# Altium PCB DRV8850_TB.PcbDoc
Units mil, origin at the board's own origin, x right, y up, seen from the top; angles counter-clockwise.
Board outline 575 x 1700 mil, 2 copper layers (Top Layer, Bottom Layer), stack 62 mil thick; 41 components, 20 nets, 99 pads, 47 vias.
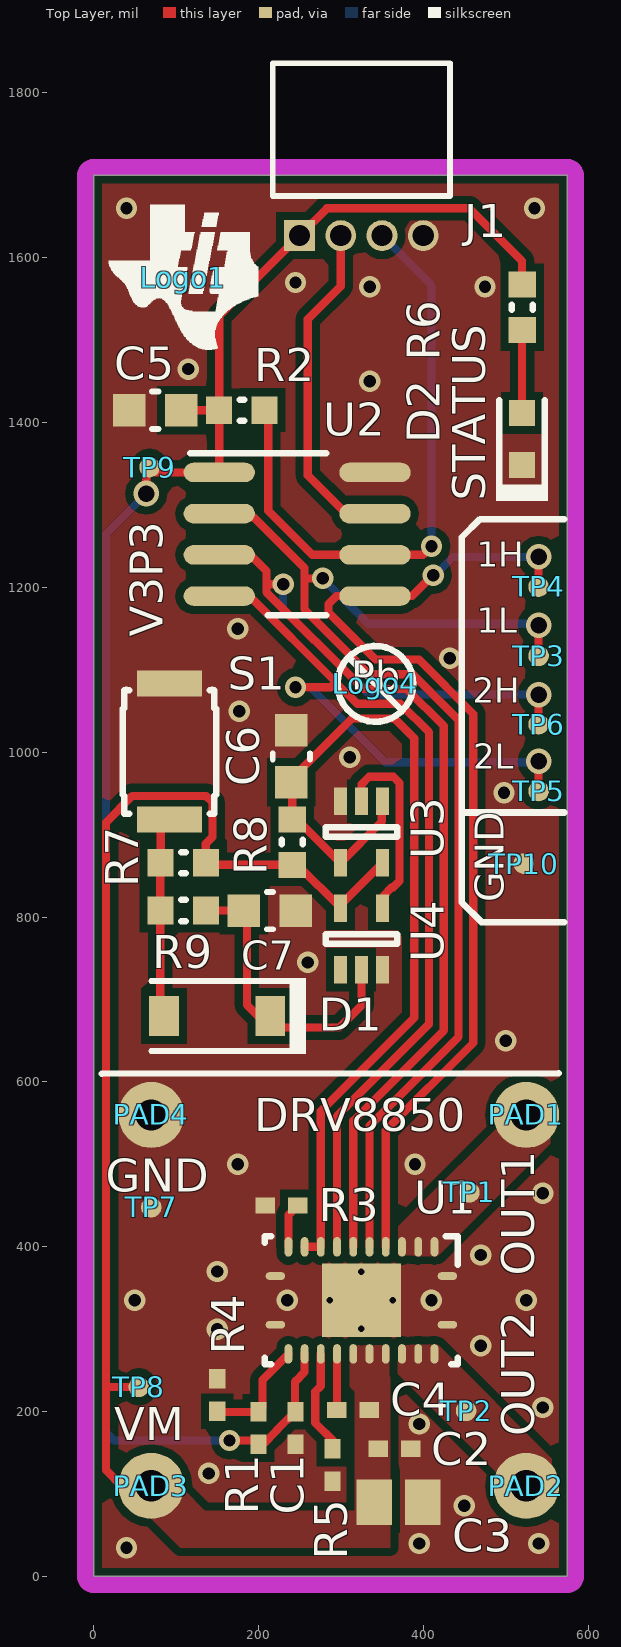
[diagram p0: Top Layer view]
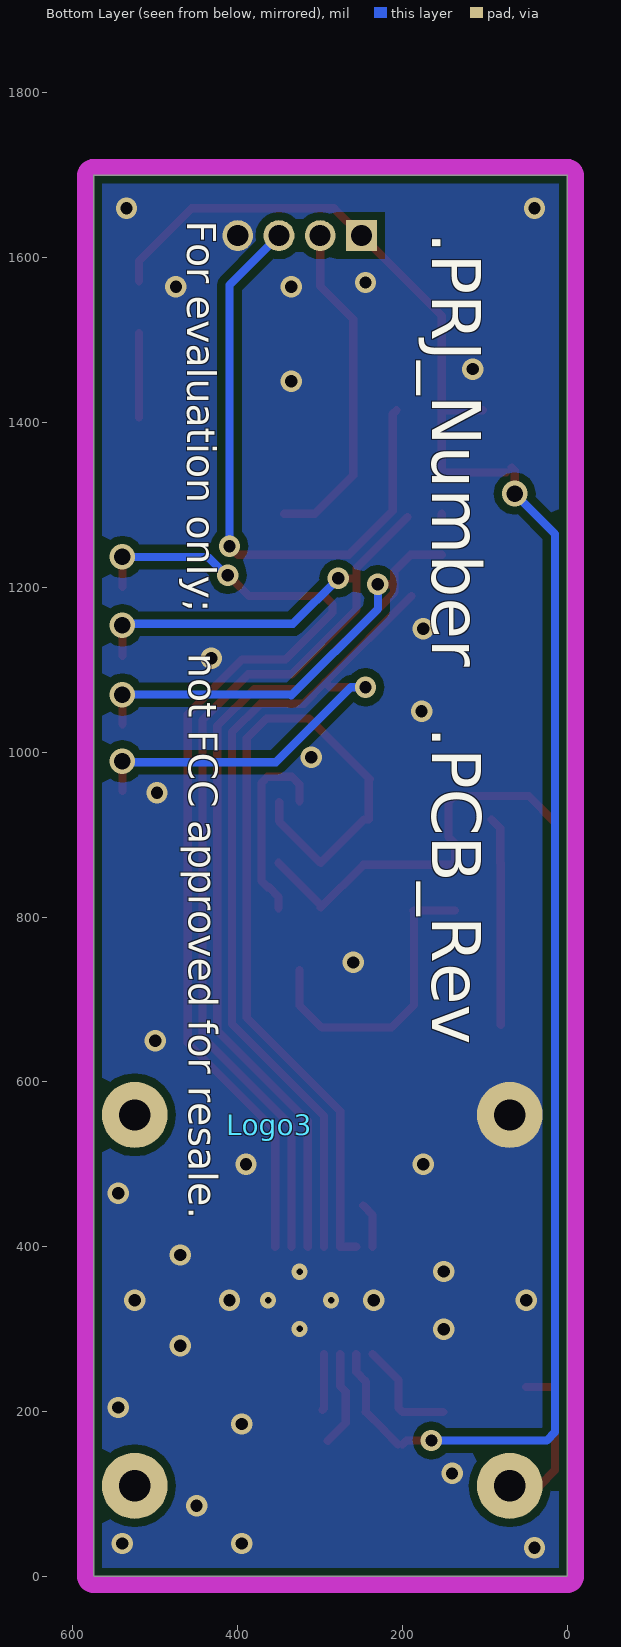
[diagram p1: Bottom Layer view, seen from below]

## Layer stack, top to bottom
Top Solder: solder mask 0.4, Solder Resist, Dk 3.5
Top Layer: signal copper 1.4
Dielectric1: core 59.2, FR-4, Dk 4.8
Bottom Layer: signal copper 1.4
Bottom Solder: solder mask 0.4, Solder Resist, Dk 3.5

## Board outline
0,0 575,0 575,1700 0,1700

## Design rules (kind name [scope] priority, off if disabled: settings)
AcuteAngle [All] p1: minimum=4.50000000000000E+0001 checktracksonly=FALSE
AssemblyTestPointUsage [All] p1: valid=2
Clearance Clearance_Keepouts [((IsTrack Or IsArc) And Not InPoly) And IsFree and IsKeepOut vs ((IsTrack Or IsArc) And Not InPoly) And IsFree and IsKeepOut] p1: gap=0
Clearance Clearance_BoardEdge_MountingHoles [OnCopper and InComponentClass('Mounting Holes') vs IsKeepOut] p2: gap=40
Clearance Clearance_BoardEdge_Poly [OnCopper and InPoly vs IsKeepOut] p3: gap=10
Clearance Clearance_BoardEdge [OnCopper and Not InComponentClass('Logo') and not InComponentClass('FiducialMark') and not InRegion(1000,500,4000,800) and Not IsKeepout vs IsKeepOut] p4: gap=10
Clearance Clearance_Poly [InPolygon] p5: gap=10
Clearance [All] p6: gap=7.87
ComponentClearance ComponentClearance_MountingHoles_FiducialMarks [InComponentClass('Mounting Holes') vs InComponentClass('FiducialMark')] p1: gap=50 collisioncheckmode=3 verticalgap=10 showdistances=FALSE
ComponentClearance ComponentClearance_Shunt [InComponentClass('Header') vs InComponentClass('Shunt')] p2: gap=0 collisioncheckmode=3 verticalgap=0 showdistances=FALSE
ComponentClearance ComponentClearance_Logo [InComponentClass('Logo')] p3: gap=40 collisioncheckmode=3 verticalgap=10 showdistances=FALSE
ComponentClearance ComponentClearance_ScrewToNut [(HasFootprint('NY PMS 440 0025 PH')) vs (HasFootprint('Keystone_1902C'))] p4: gap=5 collisioncheckmode=3 verticalgap=10 showdistances=FALSE
ComponentClearance ComponentClearance_MountingHoles [InComponentClass('Mounting Holes')] p5: gap=250 collisioncheckmode=3 verticalgap=100000 showdistances=FALSE
ComponentClearance ComponentClearance_SmallPassives [HasFootprint('0201*') or HasFootprint('0402*') or HasFootprint('0508') or HasFootprint('0603*') or HasFootprint('0612') or HasFootprint('0805*') or HasFootprint('0815*') or HasFootprint('0830*') or HasFootprint('1206*') or HasFootprint('1210*') or HasFootprint('1808*') or HasFootprint('1812*') or HasFootprint('1825*') or HasFootprint('2010*') or HasFootprint('2220*') or HasFootprint('2225*') or HasFootprint('2512*') or HasFootprint('2728*') or HasFootprint('3518*') vs HasFootprint('0201*') or HasFootprint('0402*') or HasFootprint('0508') or HasFootprint('0603*') or HasFootprint('0612') or HasFootprint('0805*') or HasFootprint('0815*') or HasFootprint('0830*') or HasFootprint('1206*') or HasFootprint('1210*') or HasFootprint('1808*') or HasFootprint('1812*') or HasFootprint('1825*') or HasFootprint('2010*') or HasFootprint('2220*') or HasFootprint('2225*') or HasFootprint('2512*') or HasFootprint('2728*') or HasFootprint('3518*')] p6: gap=20 collisioncheckmode=3 verticalgap=10 showdistances=FALSE
ComponentClearance ComponentClearance_THtoSMT [IsThruComponent vs IsSMTComponent] p7: gap=30 collisioncheckmode=3 verticalgap=30 showdistances=FALSE
ComponentClearance ComponentClearance_THtoTH [IsThruComponent vs IsThruComponent] p8: gap=60 collisioncheckmode=3 verticalgap=30 showdistances=FALSE
ComponentClearance [All] p9: gap=12 collisioncheckmode=3 verticalgap=10 showdistances=FALSE
DiffPairsRouting [All] p1: maxlimit=100 minlimit=10 mostfreqgap=10 toplayer_minwidth=15 toplayer_maxwidth=15 toplayer_prefwidth=15 bottomlayer_minwidth=15 bottomlayer_maxwidth=15 bottomlayer_prefwidth=15 maxuncoupledlength=1000
FabricationTestPointUsage TestPointUsage [All] p1: valid=2 allowmultiple=FALSE
FabricationTestpoint Testpoint [All] p1: side=3 testpointundercomponent=TRUE minsize=40 maxsize=100 preferedsize=60 minholesize=0 maxholesize=40 preferedholesize=32 testpointgrid=1 allowsidetop=TRUE allowsidebottom=TRUE usegrid=TRUE gridtolerance=0.01
FanoutControl Fanout_LCC [IsLCC] p1: bgadir=Out bgaviamode=Centered fanoutstyle=Auto fanoutdirection=Alternating viagrid=1 // Fanout_LCC (Default Rule)
FanoutControl Fanout_BGA [IsBGA] p2: bgadir=Out bgaviamode=Centered fanoutstyle=Auto fanoutdirection=Alternating viagrid=1 // Fanout_BGA (Default Rule)
FanoutControl Fanout_Default [All] p4: bgadir=Out bgaviamode=Centered fanoutstyle=Auto fanoutdirection=Alternating viagrid=1 // Fanout_Default (Default Rule)
FanoutControl Fanout_Small [(CompPinCount < 5)] p5: bgadir=Out bgaviamode=Centered fanoutstyle=Auto fanoutdirection=OutThenIn viagrid=1 // Fanout_Small (Default Rule)
HoleSize [All] p1: absolutevalues=TRUE maxlimit=251 minlimit=7.8 maxpercent=80.000 minpercent=20.000
MinimumAnnularRing MinimumAnnularRing_ThermalPadVias [IsVia and InAnyComponent] p1: minimumring=5.91
MinimumAnnularRing [All] p2: minimumring=5.5
MinimumSolderMaskSliver MinimumSolderMaskSliver_Logo [InComponentClass('Logo') vs InComponentClass('Logo')] p1: minsoldermaskwidth=0.7
MinimumSolderMaskSliver [All] p2: minsoldermaskwidth=3.94
PlaneConnect [All] p1: planeconnectstyle=Direct reliefexpansion=10 reliefentries=4 reliefconductorwidth=10 reliefairgap=10
PolygonConnect [All] p1: connectstyle=Direct reliefconductorwidth=10 reliefentries=4 polygonreliefangle="90 Angle" airgapwidth=10
RoutingVias ThermalPadVias [IsVia and InAnyComponent] p1: holewidth=7.87 width=19.68 viastyle="Through Hole" minholewidth=7.87 minwidth=19.68 maxholewidth=12.99 maxwidth=23.62
RoutingVias [All] p2: holewidth=16 width=34 viastyle="Through Hole" minholewidth=7.87 minwidth=26 maxholewidth=40 maxwidth=65
SilkToBoardRegionClearance [Not ((IsComment or IsDesignator) And (Hide <> 'False')) and not InRegion(1000,500,4000,800)] p1:
SilkToSilkClearance SilkToSilkClearance_Pb-FreeLogo [(HasFootprint('Pb-Free_Overlay_Medium') OR HasFootprint('Pb-Free_Overlay_Small')) vs (HasFootprint('Pb-Free_Overlay_Medium') OR HasFootprint('Pb-Free_Overlay_Small'))] p1: silktosilkclearance=0
SilkToSilkClearance [All] p2: silktosilkclearance=5
SilkToSolderMaskClearance "Silk to Solder Mask Opening" [All] p1: minsilkscreentomaskgap=1 clearancetoexposedcopper=FALSE
SolderMaskExpansion [All] p1: expansion=1.97
UnpouredPolygon [All] p1: allowunpoured=FALSE
Width [All] p1: maxlimit=100 minlimit=6 preferedwidth=10 checkconnectedcopper=TRUE
14 further rules are at their usual default settings.

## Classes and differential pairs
component class Logo: Logo1

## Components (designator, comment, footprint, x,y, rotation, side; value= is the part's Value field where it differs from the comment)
C1 "885012105013" 0402L 245,180 r270 top
C2 "885012105016" 0402L 365,155 r0 top
C3 "885012207026" 0805_145L 370,90 r0 top
C4 "885012105016" 0402L 315,202 r0 top
C5 "885012206046" 0603_095 75,1415 r180 top
C6 "885012206046" 0603_095 240,995 r90 top
C7 "885012106017" 0603_095 214,808 r0 top
D1 "1N4148W-7-F" SOD-123 150,680 r180 top
D2 "150060VS75000" WL-SMCW_GREEN 520,1380 r90 top
J1 "851-43-004-20-001000" CONN_851-43-004-20-001000 325,1627 r180 top
Logo1 "Texas Instruments" TI_Symbol_Overlay_Small 109,1576 r0 top
Logo3 "FCC disclaimer" FCC_disclaimer_stacked 361.28,548 r270 bottom
Logo4 "Pb-Free Symbol" Pb-Free_Overlay_Small 342,1083 r0 top
PAD1 "OUT1" TESTPOINT 525,560 r0 top
PAD2 "OUT2" TESTPOINT 525,110 r90 top
PAD3 "VM" TESTPOINT 70,110 r0 top
PAD4 "GND" TESTPOINT 70,560 r0 top
R1 "CRCW0402127KFKED" 0402L 200,180 r270 top
R2 "CRCW060347K0JNEA" 0603L 180,1415 r0 top
R3 "CRCW04022K40JNED" 0402L 228,450 r180 top
R4 "CRCW040240K2FKED" 0402L 150,220 r270 top
R5 "CRCW04021K00FKED" 0402L 290,135 r90 top
R6 "CRCW060362R0JNEA" 0603L 520,1540 r90 top
R7 "CRCW060320K0JNEA" 0603L 109,866 r0 top
R8 "DNP" 0603L 241,891 r270 top
R9 "CRCW060320K0JNEA" 0603L 109,808 r180 top
S1 "SKRKAEE010" SW_SKRKAEE010 92,1001 r270 top
TP1 "OUT1" TP_25MIL-SMT 456,466 r90 top
TP2 "OUT2" TP_25MIL-SMT 452,201 r90 top
TP3 "1L" TP_25MIL-SMT 540,1117 r90 top
TP4 "1H" TP_25MIL-SMT 540,1201 r90 top
TP5 "2L" TP_25MIL-SMT 540,953 r90 top
TP6 "2H" TP_25MIL-SMT 540,1034 r90 top
TP7 "GND" TP_25MIL-SMT 70,448 r90 top
TP8 "VM" TP_25MIL-SMT 55,230 r90 top
TP9 "V3P3" TP_25MIL-SMT 68,1346 r90 top
TP10 "GND" TP_25MIL-SMT 522,865 r90 top
U1 "DRV8850RGY" RGY0024B 325,335 r270 top
U2 "MSP430G2210IDR" D0008A_N 247.05,1264.58 r0 top
U3 "SN74LVC1G80DCK" DCK0005A_N 325,903.31 r270 top
U4 "SN74LVC1G14DCK" DCK0005A_N 325,773.31 r90 top

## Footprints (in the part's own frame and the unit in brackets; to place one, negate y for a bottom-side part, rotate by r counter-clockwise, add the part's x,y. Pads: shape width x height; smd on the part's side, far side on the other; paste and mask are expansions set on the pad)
0402L [mm] "0402 from SM-752 data"
  rect 0.6x0.5 smd: 1(-0.5,0) 2(0.5,0)
  body extent -0.55,-0.3 0.55,0.3, height 0.6
0603_095 [mm] "0603_095"
  rect 1x1 smd: 1(-0.8,0) 2(0.8,0)
  silkscreen extent -0.1,-0.58 0.1,0.58, body extent -0.87,-0.48 0.87,0.48, height 0.95
0603L [mm] "0603 from SM-752 data"
  rect 0.8x0.85 smd: 1(-0.7,0) 2(0.7,0)
  silkscreen extent -0.07,-0.33 0.07,0.33, body extent -0.87,-0.47 0.87,0.47, height 0.85
0805_145L [mm] "0805 / 1.45mm height"
  rect 1.1x1.4 smd: 1(-0.75,0) 2(0.75,0)
  body extent -1.1,-0.72 1.1,0.72, height 1.45
CONN_851-43-004-20-001000 [mm] "MILL-MAX"
  rect 0.95x0.95 hole 0.65: 1(1.905,0)
  round 0.95 hole 0.65: 2(0.635,0) 3(-0.635,0) 4(-1.905,0)
  silkscreen extent -2.73,-5.31 2.73,-1.22, body extent -2.73,-5.31 2.73,0.23, height 2.23
D0008A_N [mm] "SOIC, 8-Leads, Body 4.9x3.9mm, Pitch 1.27mm, IPC Medium Density"
  oval 2.2x0.6 smd: 1(-2.4,1.905) 2(-2.4,0.635) 3(-2.4,-0.635) 4(-2.4,-1.905) 5(2.4,-1.905) 6(2.4,-0.635) 7(2.4,0.635) 8(2.4,1.905)
  silkscreen extent -3.3,-2.5 0.9,2.5, body extent -3,-2.45 3,2.45, height 1.63
DCK0005A_N [mm] "SOT353, 5-Leads, Body 2x1.3mm, Pitch 0.65mm, Lead Span 2.1mm, IPC Medium Density"
  rect 0.85x0.4 smd: 1(-0.95,0.65) 2(-0.95,0) 3(-0.95,-0.65) 4(0.95,-0.65) 5(0.95,0.65)
  silkscreen extent -0.15,-1.1 0.15,1.1, body extent -1.14,-1 1.14,1, height 0.94
FCC_disclaimer_stacked [mil]
Pb-Free_Overlay_Small [mil]
  silkscreen extent -46,-46 46,46
RGY0024B [mm] "QFN, 24-Leads, Body 5.5x3.5mm, Pitch 0.5mm, Thermal Pad 4.05x2.05mm, TI Recommended"
  oval 0.24x0.6 smd: 1(-0.75,2.65) 12(-0.75,-2.65) 13(0.75,-2.65) 24(0.75,2.65)
  oval 0.6x0.24 smd: 2(-1.65,2.25) 3(-1.65,1.75) 4(-1.65,1.25) 5(-1.65,0.75) 6(-1.65,0.25) 7(-1.65,-0.25) 8(-1.65,-0.75) 9(-1.65,-1.25) 10(-1.65,-1.75) 11(-1.65,-2.25) 14(1.65,-2.25) 15(1.65,-1.75) 16(1.65,-1.25) 17(1.65,-0.75) 18(1.65,-0.25) 19(1.65,0.25) 20(1.65,0.75) 21(1.65,1.25) 22(1.65,1.75) 23(1.65,2.25)
  rect 2.26x2.44 smd paste-1.2: 25(0,0)
  silkscreen extent -1.97,-2.98 1.97,2.98, body extent -1.83,-2.83 1.83,2.82, height 1.01
SOD-123 [mm] "On Semi recommended land pattern"
  rect 0.915x1.22 smd: 1(-1.637,0) 2(1.637,0)
  silkscreen extent -2.74,-1.17 2.03,1.17, body extent -1.93,-0.9 1.93,0.9, height 1.35
SW_SKRKAEE010 [mm] "Alps recommended land pattern"
  rect 0.8x2 smd: 1(-2.1,0) 2(2.1,0)
  silkscreen extent -1.9,-1.44 1.92,1.44, body extent -2.4,-1.45 2.4,1.45, height 1.96
TESTPOINT [mil]
  round 80 hole 37.99: 1(0,0)
TI_Symbol_Overlay_Small [mil]
  silkscreen extent -90,-88 91,88
TP_25MIL-SMT [mil]
  round 25 smd mask-2.5: 1(0,0)
WL-SMCW_GREEN [mm] "WURTH"
  rect 0.8x0.8 smd: 1(-0.8,0) 2(0.8,0)
  silkscreen extent -1.9,-0.8 1.2,0.8, body extent -0.85,-0.45 0.85,0.45, height 0.8

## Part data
C1: "CAP, CERM, 2.2 µF, 10 V, +/- 20%, X5R, 0402"
C2 C4: "CAP, CERM, 0.1 µF, 16 V, +/- 20%, X5R, 0402"
C3: "CAP, CERM, 10 µF, 10 V, +/- 10%, X7R, 0805"
C5 C6: "CAP, CERM, 0.1 µF, 16 V, +/- 10%, X7R, 0603_095"
C7: "CAP, CERM, 1 µF, 16 V, +/- 20%, X5R, 0603_095"
D1: "Diode, Ultrafast, 100 V, 0.15 A, SOD-123"
D2: "LED, Green, SMD"
J1: "SOCKET .050\" GRID SIP 4 POS R/A, TH"
Logo1: library part TI_Logo, "Texas Instrument Corporate Signature"
Logo3: library part FCC_disclaimer, "FCC_disclaimer"
Logo4: library part Pb-Free
PAD1 PAD2 PAD3 PAD4 TP1 TP2 TP3 TP4 TP5 TP6 TP7 TP8 TP9 TP10: library part TESTPOINT, "TEST POINT.  No entry in BOM."
R1: "RES, 127k ohm, 1%, 0.063W, 0402"
R2: "RES, 47k ohm, 5%, 0.1W, 0603"
R3: "RES, 2.4k ohm, 5%, 0.063W, 0402"
R4: "RES, 40.2k ohm, 1%, 0.063W, 0402"
R5: "RES, 1.00k ohm, 1%, 0.063W, 0402"
R6: "RES, 62, 5%, 0.1 W, 0603"
R7 R9: "RES, 20k ohm, 5%, 0.1W, 0603"
R8: library part CRCW06030000Z0EA, "RES, 0 ohm, 5%, 0.1W, 0603"
S1: "Switch, Push Button, SMD"
U1: "Low-Voltage H-Bridge IC With LDO Regulator, RGY0024B"
U2: "MIXED SIGNAL MICROCONTROLLER, D0008A"
U3: library part SN74LVC1G80DBV, "IC, Single Positive-Edge-Triggered D-Type Flip-Flop"
U4: "IC, Single Schmitt-Trigger Inverter"

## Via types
v1: diameter 26, hole 15, Top Layer to Bottom Layer, tented both sides, 36 vias
v2: diameter 31, hole 20, Top Layer to Bottom Layer, 5 vias
v3: diameter 19.68, hole 7.87, Top Layer to Bottom Layer, 4 vias
v4: diameter 26, hole 15, Top Layer to Bottom Layer, 2 vias

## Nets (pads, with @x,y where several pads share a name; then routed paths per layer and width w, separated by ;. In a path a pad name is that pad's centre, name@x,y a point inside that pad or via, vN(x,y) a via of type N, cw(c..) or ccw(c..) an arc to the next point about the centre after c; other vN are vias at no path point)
GND: C1.2 C2.2 C3.2 C5.2 C6.2 C7.2 D2.1 J1.4 PAD4.1 R3.2 R4.1 R5.1 S1.1 TP7.1 TP10.1 U1.1 U1.12 U1.13 U1.24 U1.25 U2.8 U3.3 U4.3
  other v1: 40,35 395,40 540,40 450,86 140,125 395,185 545,205 470,280 150,300 50,335 235,335 410,335 525,335 150,370 470,390 545,465 175,500 390,500 500,650 260,745 498,951 311,994 177,1050 432,1114 175,1150 335,1450 115,1465 335,1565 475,1565 245,1570 40,1660 535,1660
  other v3: 325,300.35 286.81,335 363.19,335 325,369.65
IN1H: TP4.1 U1.5 U2.5 | length 1248.7
  Top Layer w10: U1.5 354.53,541.25 460.71,647.43 460.71,1046.57 394.78,1112.5 342.21,1112.5 285,1169.71 285,1180 294.58,1189.58 U2.5 386.58,1189.58 v1(412,1215) ; TP4.1 v2(540,1237)
  Bottom Layer w10: v1(412,1215) 410,1217 413,1220 416,1217 436,1237 v2(540,1237)
IN1L: TP3.1 U1.6 U2.2 | length 1410.4
  Top Layer w10: U2.2@152.56,1283.08 U2.2 ; U2.2@194.17,1285.55 256,1223.72 256,1173.43 334.81,1094.62 387.38,1094.62 442.83,1039.17 442.83,654.83 334.84,546.84 U1.6 ; 258,1211 v4(278,1211) ; TP3.1 v2(540,1154)
  Bottom Layer w10: v4(278,1211) 333,1156 v2@538,1156
IN2H: TP6.1 U1.7 U2.3 | length 1489.7
  Top Layer w10: U2.3 190.42,1239.58 210,1220 210,1194.15 327.4,1076.75 379.97,1076.75 424.96,1031.76 424.96,662.68 315.16,552.88 U1.7 ; 211,1204 v4(230,1204) ; TP6.1 v2(540,1070)
  Bottom Layer w10: v4(230,1204) 230,1174.15 335.15,1069 336.15,1070 v2(540,1070)
IN2L: TP5.1 U1.8 U2.4 | length 1375.9
  Top Layer w10: U2.4@189.29,1189.58 293.87,1085 ; v1(245,1079) 287.87,1079 293.87,1085 ; U1.8 295.47,558.47 407.09,670.09 407.09,1024.36 372.57,1058.87 320,1058.87 293.87,1085 ; TP5.1 v2(540,989)
  Bottom Layer w10: v1(245,1079) 262.59,1079 353.59,988 v2@539,988
NetC4_1: C4.1 U1.17 | length 68.8
  Top Layer w10: U1.17 295.47,203.84 C4.1@297.32,202
NetC7_1: C7.1 D1.1 R9.1 U4.2 | length 368.6
  Top Layer w10: R9.1 C7.1@186.44,808 ; C7.1@186.06,807.62 186.06,693.41 213.47,666 298.21,666 325,692.79 U4.2
NetD1_2: D1.2 R7.1 R9.2 S1.2 | length 252.2
  Top Layer w10: R7.1@81,865 D1.2@81.06,669.48 ; R7.1 81.44,907.76 S1.2
NetD2_2: D2.2 R6.1 | length 102.4
  Top Layer w10: D2.2@520,1406.09 R6.1@520,1508.5
NetR1_1: R1.1 R4.2 U1.14 | length 134.8
  Top Layer w10: R4.2@150.63,199.68 R1.1 204.95,204.63 204.95,238.57 U1.14
NetR3_1: R3.1 U1.11 | length 54.7
  Top Layer w10: U1.11 236.42,438.73 R3.1
NetR5_2: R5.2 U1.16 | length 117.5
  Top Layer w10: U1.16 275.79,231.1 269,224.32 269,186.43 R5.2@290.95,164.48
NetU3_2: U3.2 U4.4 | length 235.3
  Top Layer w10: U3.2 325,961.2 334.12,970.32 363.8,970.32 371.34,962.78 371.34,843.85 363.8,836.31 362.31,836.31 350.59,824.59 U4.4
OUT1: PAD1.1 TP1.1 U1.2 U1.3 U1.4
OUT2: PAD2.1 TP2.1 U1.21 U1.22 U1.23
SBWTCK: J1.2 U2.7 | length 410.9
  Top Layer w10: J1.2 300,1565.59 260,1525.59 260,1335.88 306.3,1289.58 U2.7 U2.7@344.05,1289.58
SBWTDIO: J1.3 R2.2 U2.6 | length 750.2
  Top Layer w10: R2.2 212.05,1410.51 212.05,1292.95 265.42,1239.58 U2.6 399.63,1239.58 v1(410.05,1250)
  Bottom Layer w10: J1.3 410,1567 410,1360 410.05,1359.95 v1(410.05,1250)
TOGGLE: C6.1 R8.1 U1.9 U1.10 U3.1 U3.4 | length 1098.1
  Top Layer w10: C6.1@240,967.44 C6.1@241,968.44 ; U1.10 U1.9 275.79,564.79 389.21,678.21 389.21,1016.95 365.17,1041 313.56,1041 C6.1@241,968.44 ; U3.1@349.69,939.82 349.69,916.2 U3.4 246.76,918.56 R8.1 C6.1@241,968.44
V3P3: C1.1 C5.1 J1.1 R1.2 R2.1 R6.2 TP9.1 U1.15 U2.1 | length 2301.3
  Top Layer w10: v2(64,1314) 64,1342 TP9.1@67.58,1345.58 ; TP9.1@74.42,1339.58 U2.1 152.56,1414.88 R2.1 ; C5.1@102.56,1415 R2.1 ; v1(165,165) 195.31,165 R1.2 ; R1.2@205.63,160.31 222.28,176.97 222.28,177.46 244.51,199.68 C1.1 ; C1.1@244.32,202 244.32,236.22 ; 245.45,237.35 256.1,248.01 U1.15 ; R6.2@520,1571.5 520,1596.02 456.02,1660 283,1660 J1.1 152.44,1529.44 R2.1
  Bottom Layer w10: v2(64,1314) 15,1265 15,1239 15,250.71 15,175 25,165 v1(165,165)
VM: C2.1 C3.1 C4.2 PAD3.1 R7.2 R8.2 TP8.1 U1.18 U1.19 U1.20 U3.5 U4.5 | length 1364.1
  Top Layer w10: 15,230 TP8.1@50,230 ; PAD3.1 34,110 15,129 15,915 46.94,946.94 136.7,946.94 144.24,939.4 144.24,897.24 136.17,889.17 136.17,866.38 R7.2 139.12,863.44 R8.2 247.63,863.44 U4.5@299.41,811.66 ; U4.5@299.41,814.73 U3.5
pads on no net: U4.1

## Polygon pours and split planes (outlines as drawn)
VM on Top Layer "Top Layer-VM" (solid, remove dead copper, pour order 8): 310,281 360,281 360,35 105,35 35.96,104.04 37,119.12 37,132 50,145 69.89,145.11 135,80 142.69,80 317,80 317,132 317,224 310,231
GND on Top Layer "Top Layer-GND" (solid, remove dead copper, pour order 9): 575,0 0,0 0,1825 575,1825
OUT1 on Top Layer "Top Layer-OUT1" (solid, remove dead copper, pour order 6): 418,388.72 370,388.72 370,424.72 489.34,544.06 489.34,576.34 508,595 540.28,595 554.28,581 554.28,525
OUT2 on Top Layer "Top Layer-OUT2" (solid, remove dead copper, pour order 7): 418,281 369,281 369,246 489,126 489,94 508,75 542,75 556,89 556,143
GND on Bottom Layer "Bottom Layer-GND" (solid, remove dead copper, pour order 10): 0,0 575,0 575,1700 0,1700

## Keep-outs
Keep-Out Layer:
  lines w20: -10,0 ccw(c0,0) 0,-10 ; -10,0 ccw(c0,0) 0,-10 ; -10,0 -10,1700 ; -10,1700 cw(c0,1700) 0,1710 ; -10,1700 cw(c0,1700) 0,1710 ; 0,-10 575,-10 ; 0,1710 575,1710 ; 575,-10 ccw(c575,0) 585,0 ; 575,-10 ccw(c575,0) 585,0 ; 575,1710 cw(c575,1700) 585,1700 ; 575,1710 cw(c575,1700) 585,1700 ; 585,0 585,1700
  text ".Layer_Name" at 577,-858.49 h60

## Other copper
Top Layer:
  text ".Layer_Name" at 577,-858.49 h60
Bottom Layer:
  text ".Layer_Name" at 577,-858.49 h60

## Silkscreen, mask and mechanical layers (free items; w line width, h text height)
Top Overlay:
  lines w8: 10,610 564.61,610.43 ; 449,927 571,927 ; 571,794 470.71,794 446.83,817.88 446.83,1260.83 469,1283 571,1283
  text "STATUS" at 475,1305 h40 r90
  text "1H" at 465,1225 h30
  text "1L" at 465,1145 h30
  text "2H" at 460,1060 h30
  text "2L" at 460.71,980 h30
  text "DRV8850" at 195,540 h40
  text ".Layer_Name" at 577,-858.49 h60
Bottom Overlay:
  text ".PRJ_Number" at 164,1631 h60 r90
  text ".PCB_Rev" at 164,1031 h60 r90
  text ".Layer_Name" at 577,-858.49 h60
Top Paste:
  text ".Layer_Name" at 577,-858.49 h60
Bottom Paste:
  text ".Layer_Name" at 577,-858.49 h60
Top Solder:
  text ".Layer_Name" at 577,-858.49 h60
  text ".Layer_Name" at 577,-858.49 h60
Bottom Solder:
  text ".Layer_Name" at 577,-858.49 h60
Drill Guide:
  text ".Layer_Name" at 577,-858.49 h60
M1 Board Outline:
  the board outline again, w10
  text ".Layer_Name" at 577,-858.49 h60
M2 Board Dimensions:
  rectangle: 0,-275 125,-150
  rectangle: 125,-400 500,-275
  lines w7: 0,-275 1000,-275 ; 125,-400 125,-150 ; 250,-400 250,-150 ; 500,-400 500,-150 ; 750,-400 750,-150 ; 0,-400 1000,-400 1000,-150 0,-150 0,-400
  lines w12: 10,610 564.61,610.43
  text ".Layer_Name" at 577,-858.49 h60
M3 3D STEP Top:
  text ".Layer_Name" at 577,-858.49 h60
M4 3D STEP Bottom:
  text ".Layer_Name" at 577,-858.49 h60
M5 Assembly Top:
  lines w10: -292,-930.17 6308,-930.17 ; -292,-726.83 6310,-726.83 ; -292,-523.5 -292,-1133.5 3713,-1133.5 6310,-1133.5 6310,-523.5 -291.5,-523.5 -291.5,-1133.5 1284,-1133.5 ; 2173,-1133.5 2173,-523.5 ; 3440,-726.83 3440,-523.5 ; 4280,-726.83 4280,-523.5 ; 4902,-1140 4902,-937.17
  text "COMPONENTS MARKED 'DNP' SHOULD NOT BE POPULATED." at 1153.5,-318.5 h60
  text "ASSEMBLY VARIANT:" at 1153,-434 h60
  text ".VariantName" at 2189,-434 h60
  text "PCB VIEWED FROM TOP SIDE" at -228.5,-655.67 h60
  text "BOARD #:" at 2248,-655.67 h60
  text ".PRJ_Number" at 2793.5,-655.67 h60
  text "REV:" at 3638,-655.67 h60
  text ".PCB_Rev" at 3929.5,-655.67 h60
  text "SVN REV:" at 4476,-655.67 h60
  text ".VersionControl_RevNumber" at 4982,-655.67 h60
  text "PLOT NAME =" at -228.5,-1064.34 h60
  text ".plot_File_Name" at 577,-1064.34 h60
  text "GENERATED    :" at 2250,-1064.34 h60
  text ".Print_Date" at 3119.5,-1064.34 h60
  text ".Print_Time" at 3848.5,-1064.34 h60
  text "TEXAS INSTRUMENTS" at 5113,-1064.34 h60
M6 Assembly Bottom:
  lines w10: -292.5,-727.33 6309.5,-727.33 ; -290.5,-930.67 6309.5,-930.67 ; 1115.5,-1140.5 1115.5,-937.67 ; 1737.5,-727.33 1737.5,-524 ; 2577.5,-727.33 2577.5,-524 ; 3844.5,-1134 3844.5,-524 ; 4733.5,-1134 6309,-1134 6309,-524 -292.5,-524 -292.5,-1134 2304.5,-1134 6309.5,-1134 6309.5,-524
  text "COMPONENTS MARKED 'DNP' SHOULD NOT BE POPULATED." at 6102,-318 h60
  text ".VariantName" at 5058,-434 h60
  text "ASSEMBLY VARIANT:" at 6097,-434 h60
  text ".VersionControl_RevNumber" at 1035.5,-656.17 h60
  text "SVN REV:" at 1541.5,-656.17 h60
  text ".PCB_Rev" at 2088,-656.17 h60
  text "REV:" at 2379.5,-656.17 h60
  text ".PRJ_Number" at 3224,-656.17 h60
  text "BOARD #:" at 3769.5,-656.17 h60
  text "PCB VIEWED FROM BOTTOM SIDE" at 6246,-656.17 h60
  text "TEXAS INSTRUMENTS" at 904.5,-1064.84 h60
  text ".Print_Time" at 2169,-1064.84 h60
  text ".Print_Date" at 2898,-1064.84 h60
  text "GENERATED    :" at 3767.5,-1064.84 h60
  text ".plot_File_Name" at 5440.5,-1064.84 h60
  text "PLOT NAME =" at 6246,-1064.84 h60
M9 Title Sheet:
  drawing of 57 lines, arcs and shapes, not listed
  text "1" at 739.84,8036.5 h70
  text "2" at 3235.5,8036.5 h70
  text "3" at 5724.84,8036.5 h70
  text "4" at 8231.51,8036.5 h70
  text "5" at 10730.5,8036.5 h70
  text "6" at 13235.5,8036.5 h70
  text "A" at -416.5,6893.5 h70
  text "A" at 14383.5,6893.5 h70
  text "B" at -416.5,4513.5 h70
  text "B" at 14383.5,4513.5 h70
  text "C" at -416.5,2138.5 h70
  text "C" at 14383.5,2138.5 h70
  text "PROJECT TITLE:" at 11343.5,277.5 h45
  text ".PRJ_Title" at 11393.5,144.17 h70
  text "DESIGNED FOR:" at 11343.5,-23.5 h45
  text ".PRJ_Customer" at 11393.5,-163.5 h70
  text "D" at -416.5,-231.5 h70
  text "D" at 14383.5,-231.5 h70
  text "FILE NAME:" at 11343.5,-323.5 h45
  text ".PCB_File_Name_No_Path" at 11393.5,-443.5 h70
  text "Texas Instruments (TI) and/or its licensors do not warrant the accuracy or completeness of this specification" at 6374,-605.34 h45
  text "ENGINEER:" at 11343.5,-613.5 h45
  text "LAYOUT BY:" at 12848.5,-613.5 h45
  text "or any information contained therein. TI and/or its licensors do not warrant that this design will meet" at 6329.01,-718 h45
  text ".PRJ_Engineer" at 11393.5,-768.49 h70
  text ".PCB_Layout" at 12899,-768.49 h70
  text "the specifications, will be suitable for your application or fit for any particular purpose, or will operate in" at 6329.01,-830.67 h45
  text ".Layer_Name" at 577,-858.49 h60
  text "ALTIUM DESIGNER VERSION:" at 12848.5,-923.5 h45
  text "an implementation. TI and/or its licensors do not warrant that the design is production worthy. You should" at 6329.01,-943.33 h45
  text "completely validate and test your design implementation to confirm the system functionality for your application." at 6374,-1056 h45
  text ".print_Scale" at 11393.5,-1056.83 h70
  text ".Application_BuildNumber" at 12899,-1056.83 h70
  text "1" at 739.84,-1263.5 h70
  text "2" at 3235.5,-1263.5 h70
  text "3" at 5724.84,-1263.5 h70
  text "4" at 8231.51,-1263.5 h70
  text "5" at 10730.5,-1263.5 h70
  text "6" at 13235.5,-1263.5 h70
M10 Fab Notes:
  drawing of 185 lines, arcs and shapes, not listed
  text "DESIGN INFORMATION" at 12381.02,5910 h60
  text "MIN. TRACK WIDTH:" at 11736.46,5730 h60
  text "8" at 12832.7,5730 h60
  text "MIL" at 12987.46,5730 h60
  text "MIN. CLEARANCE:" at 11736.46,5598 h60
  text "0.2" at 12772.7,5598 h60
  text "mm" at 12987.46,5598 h60
  text "MIN. VIA PAD SIZE:" at 11736.46,5466 h60
  text "24" at 12802.71,5466 h60
  text "MIL" at 12987.46,5466 h60
  text "0.05mm (2MIL)" at 12431.46,5324.29 h60
  text "MINIMUM ANNULAR RING" at 11407.23,5320 h60
  text "EXTERNAL" at 13139.46,5320 h60
  text "PER" at 11607.23,5202 h60
  text "IPC-D-275 CLASS 2 LEVEL C" at 11827.23,5202 h60
  text "MIL, HOLES" at 13315.46,5089.71 h60
  text "+/-" at 12923,5089 h60
  text "+/-" at 13777,5089 h60
  text "REGISTRATION TOLERANCES:" at 11407.23,5084 h60
  text "METAL" at 12607,5084 h60
  text "5" at 13183.2,5084 h60
  text "3" at 14016.2,5084 h60
  text "MIL" at 14132.46,5084 h60
  text "MATERIAL:" at 11332.46,4874.54 h60
  text "FR-4 High Tg" at 12318.9,4734.21 h60
  text "FR-408" at 11753.46,4725.64 h60
  text "X" at 12165.46,4725.64 h60
  text "OTHER" at 13241.46,4725.64 h60
  text "62 MIL (1.6mm) +/-10%" at 12073.56,4562.92 h60
  text "THICKNESS:" at 11407.23,4558.64 h60
  text "X" at 11945.4,4558.64 h60
  text "OTHER" at 13358.46,4558.64 h60
  text "TOLERANCE:" at 11407.23,4400.64 h60
  text "X" at 12246.53,4400.64 h60
  text "ANSI IPC-6012 TYPE 3 CLASS 2" at 12433.48,4400.64 h60
  text "OTHER +/-" at 12433.46,4244.64 h60
  text "BOW & TWIST:" at 11407.23,4087.64 h60
  text "X" at 12246.53,4087.64 h60
  text "ANSI IPC-6012 TYPE 3 CLASS 2" at 12433.48,4087.64 h60
  text "OTHER +/-" at 12433.46,3929.13 h60
  text "DRILLING:" at 11332.46,3790.64 h60
  text "REFERENCE:" at 11407.23,3673.64 h60
  text "X" at 12055.46,3673.64 h60
  text "AS SHOWN" at 12242.46,3673.64 h60
  text "X" at 12956.46,3673.64 h60
  text "NC_DRILL FILES" at 13093.46,3673.64 h60
  text "PTH MIN COPPER THICKNESS:" at 11407.23,3515.64 h60
  text "X" at 12757.46,3515.64 h60
  text "1MIL" at 12894.46,3515.64 h60
  text "OTHER" at 13391.46,3515.64 h60
  text "BOARD FINISH:" at 11332.46,3356.64 h60
  text "SILKSCREEN:" at 11487.68,3238.64 h60
  text "X" at 12436.46,3238.64 h60
  text "TOP" at 12562.46,3238.64 h60
  text "X" at 12946.46,3238.64 h60
  text "BOTTOM" at 13073.46,3238.64 h60
  text "SILKSCREEN COLOR:" at 11487.68,3071.64 h60
  text "X" at 12435.42,3071.64 h60
  text "WHITE" at 12562.46,3071.64 h60
  text "OTHER" at 13073.46,3071.64 h60
  text "SOLDER RESIST COLOR:" at 11487.68,2901.64 h60
  text "X" at 12055.42,2742.44 h60
  text "GREEN" at 12182.46,2742.44 h60
  text "BLUE" at 12773.46,2742.44 h60
  text "OTHER" at 13311.46,2742.44 h60
  text "IMMERSION GOLD (ENIG)" at 12393.46,2553.92 h60
  text "ENEPIG" at 13731,2550.64 h60
  text "SURFACE FINISH:" at 11332.46,2549.64 h60
  text "X" at 12206.51,2549.64 h60
  text "IMM. TIN/SILVER OR EQUIV" at 11662,2392.64 h60
  text "OTHER" at 13093.46,2392.64 h60
  text "ARRAY/PANEL:" at 11332.46,2213.64 h60
  text "CUT AND TRIM PER MECH LAYER 1" at 12393.46,2209.35 h60
  text "N.C. ROUTE" at 12393.46,2057.64 h60
  text "X" at 13072.46,2057.64 h60
  text "V. SCORE" at 13259.46,2057.64 h60
  text "CERTIFICATION:" at 11332.46,1920.64 h60
  text "MATERIALS AND WORKMANSHIP FOR ALL PCBS" at 12057.46,1920.64 h60
  text "TO MEET OR EXCEED THE REQUIREMENTS OF:" at 12057.46,1822.64 h60
  text "X" at 11683.96,1686.13 h60
  text "ANSI IPC-A-600F CLASS ->" at 11822.96,1686.13 h60
  text "X" at 13462.02,1686.13 h60
  text "2" at 13580.96,1686.14 h60
  text "1" at 13265.96,1684.64 h60
  text "3" at 13934.96,1684.64 h60
  text "X" at 11686.02,1526.64 h60
  text "UL 94V-0" at 11822.96,1526.64 h60
  text "X" at 12498.02,1526.64 h60
  text "RoHS" at 12634.96,1526.64 h60
  text "OTHER" at 13279.36,1526.64 h60
  text "PER ORDER" at 13676.42,1526.64 h60
  text "ADDITIONAL REQUIREMENTS:" at 11332.46,1385.64 h60
  text "MICROSECTION:" at 11407.23,1270.64 h60
  text "YES" at 12312.96,1270.64 h60
  text "REQUIRED" at 13174.46,1114.49 h60
  text "BARE BOARD ELEC. TEST:" at 11407.23,1111.64 h60
  text "NONE" at 12712.96,1111.64 h60
  text "X" at 13047.46,1111.64 h60
  text "PER ORDER" at 13766.46,1111.64 h60
  text "MANUFACTURER'S UL:" at 11407.23,954.64 h60
  text "RAIL" at 12572.96,950.35 h60
  text "METAL" at 13064.77,950.35 h60
  text "X" at 13440,950 h60
  text "SILK" at 13576.46,950.35 h60
  text ".Layer_Name" at 577,-858.49 h60
M11 Gerber Information:
  lines w10: -292,-930.17 6308,-930.17 ; -292,-726.83 6310,-726.83 ; -292,-523.5 -292,-1133.5 3713,-1133.5 6310,-1133.5 6310,-523.5 -291.5,-523.5 -291.5,-1133.5 1284,-1133.5 ; 2173,-1133.5 2173,-523.5 ; 3440,-726.83 3440,-523.5 ; 4280,-726.83 4280,-523.5 ; 4902,-1140 4902,-937.17
  text "ALL ARTWORK VIEWED FROM TOP SIDE" at -228.5,-655.67 h60
  text "BOARD #:" at 2248,-655.67 h60
  text ".PRJ_Number" at 2793.5,-655.67 h60
  text "REV:" at 3638,-655.67 h60
  text ".PCB_Rev" at 3929.5,-655.67 h60
  text "SVN REV:" at 4476,-655.67 h60
  text ".VersionControl_RevNumber" at 4982,-655.67 h60
  text "LAYER NAME =" at -228.5,-858.49 h60
  text "PLOT NAME =" at -228.5,-1064.34 h60
  text ".plot_File_Name" at 577,-1064.34 h60
  text "GENERATED    :" at 2250,-1064.34 h60
  text ".Print_Date" at 3119.5,-1064.34 h60
  text ".Print_Time" at 3848.5,-1064.34 h60
  text "TEXAS INSTRUMENTS" at 5113,-1064.34 h60
M12 Stackup:
  drawing of 191 lines, arcs and shapes, not listed
  text "Layer" at 9790.58,7830 h60
  text "Name" at 10200.49,7830 h60
  text "Material" at 11130.23,7830 h60
  text "Thickness" at 11990,7830 h60
  text "Constant" at 12639.84,7830 h60
  text "Board Layer Stack" at 13209.7,7830 h60
  text "1" at 9790.58,7710 h60
  text "Top Overlay" at 10200.49,7710 h60
  text "2" at 9790.58,7590 h60
  text "Top Solder" at 10200.49,7590 h60
  text "Solder Resist" at 11130.23,7590 h60
  text "0.40mil" at 11990,7590 h60
  text "3.5" at 12639.84,7590 h60
  text "3" at 9790.58,7470 h60
  text "Top Layer" at 10200.49,7470 h60
  text "Copper" at 11130.23,7470 h60
  text "1.40mil" at 11990,7470 h60
  text "4" at 9790.58,7350 h60
  text "Dielectric1" at 10200.49,7350 h60
  text "FR-4" at 11130.23,7350 h60
  text "59.20mil" at 11990,7350 h60
  text "4.8" at 12639.84,7350 h60
  text "5" at 9790.58,7230 h60
  text "Bottom Layer" at 10200.49,7230 h60
  text "Copper" at 11130.23,7230 h60
  text "1.40mil" at 11990,7230 h60
  text "6" at 9790.58,7110 h60
  text "Bottom Solder" at 10200.49,7110 h60
  text "Solder Resist" at 11130.23,7110 h60
  text "0.40mil" at 11990,7110 h60
  text "3.5" at 12639.84,7110 h60
  text "7" at 9790.58,6990 h60
  text "Bottom Overlay" at 10200.49,6990 h60
  text ".Layer_Name" at 577,-858.49 h60
M13 Component Bodies Top:
  text ".Layer_Name" at 577,-858.49 h60
M14 Component Bodies Bottom:
  text ".Layer_Name" at 577,-858.49 h60
M15 Courtyards Top:
  text ".Layer_Name" at 577,-858.49 h60
M16 Courtyards Bottom:
  text ".Layer_Name" at 577,-858.49 h60
Drill Drawing:
  circle w10: c910.8,1506.18 r20.74
  lines w10: 890.05,1029.12 931.54,1029.12 910.8,987.64 890.05,1029.12 ; 890.05,1122.46 900.42,1122.46 910.8,1112.09 921.17,1122.46 931.54,1122.46 921.17,1132.83 931.54,1143.2 921.17,1143.2 910.8,1153.57 900.42,1143.2 890.05,1143.2 900.42,1132.83 890.05,1122.46 ; 890.05,1236.53 910.8,1246.91 931.54,1236.53 921.17,1257.28 931.54,1278.02 910.8,1267.65 890.05,1278.02 900.42,1257.28 890.05,1236.53 ; 890.05,1360.99 931.54,1360.99 931.54,1402.47 890.05,1402.47 890.05,1360.99
  lines w12: 833,950.3 2862.36,950.3 ; 833,1572.55 2862.36,1572.55 ; 1181.16,825.85 1181.16,1697 ; 1523.27,825.85 1523.27,1697 ; 2170.27,825.85 2170.27,1697 ; 2439.62,825.85 2439.62,1697 ; 833,825.85 2862.36,825.85 2862.36,1697 833,1697 833,825.85
  text "Symbol" at 907.67,1609.89 h72
  text "Quantity" at 1218.5,1609.89 h72
  text "Finished Hole Size" at 1560.6,1609.89 h72
  text "Plated" at 2207.6,1609.89 h72
  text "Hole Type" at 2476.95,1609.89 h72
  text "4" at 1218.5,1485.43 h60
  text "7.87mil (0.200mm)" at 1560.6,1485.43 h60
  text "PTH" at 2207.6,1485.43 h60
  text "Round" at 2476.95,1485.43 h60
  text "38" at 1218.5,1360.99 h60
  text "15.00mil (0.381mm)" at 1560.6,1360.99 h60
  text "PTH" at 2207.6,1360.99 h60
  text "Round" at 2476.95,1360.99 h60
  text "5" at 1218.5,1236.53 h60
  text "20.00mil (0.508mm)" at 1560.6,1236.53 h60
  text "PTH" at 2207.6,1236.53 h60
  text "Round" at 2476.95,1236.53 h60
  text "4" at 1218.5,1112.09 h60
  text "25.59mil (0.650mm)" at 1560.6,1112.09 h60
  text "PTH" at 2207.6,1112.09 h60
  text "Round" at 2476.95,1112.09 h60
  text "4" at 1218.5,987.64 h60
  text "37.99mil (0.965mm)" at 1560.6,987.64 h60
  text "PTH" at 2207.6,987.64 h60
  text "Round" at 2476.95,987.64 h60
  text "55 Total" at 1218.5,863.18 h60
  text ".Layer_Name" at 577,-858.49 h60

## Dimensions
0,1700 to 0,0 on M2 Board Dimensions
0,-400 to 1000,-400 on M2 Board Dimensions
575,1700 to 0,1700 on M2 Board Dimensions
